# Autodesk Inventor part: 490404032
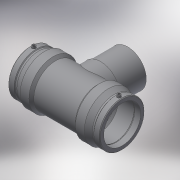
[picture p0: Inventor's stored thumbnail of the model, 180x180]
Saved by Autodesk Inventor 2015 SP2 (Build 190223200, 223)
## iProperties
Created: 2017-06
Part Number: 490404032
Material: Generic
Description: PLASSON TEE 32-32-32
Document SubType Name: Modeling
Designer: KIM
Mass: 90.0221 g
Surface Area: 377.919 cm^2
Volume: 90.0221 cm^3
Density: 1 g/cm^3
Appearance: Default
Author: KIM
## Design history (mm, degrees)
derived "490404.ipt"
feature "Solid1::490404.ipt"
tag "TaggingFeature1"
body "Solid1"
other parameters: "d0" = 104, "d1" = 32, "d2" = 44, "d3" = 39, "d4" = 26, "d5" = 39.6, "d6" = 30.4, "d7" = 32, "d8" = 168 deg, "d10" = 15.6, "d11" = 5.2, "d13" = 104, "d14" = 17.6296, "d17" = 28.8, "d18" = 32, "d19" = 3.52592, "d20" = 168 deg, "d22" = 40.92, "d23" = 44, "d24" = 39.6924, "d25" = 135 deg, "d26" = 72.8, "d27" = 135 deg, "d29" = 43, "d30" = 15, "d31" = 41.6, "d34" = 5 deg, "d35" = 15, "d39" = 5 deg, "d40" = 9.6, "d41" = 4.8, "d42" = 6, "d43" = 0, "d45" = 4, "d46" = 14, "d47" = 0, "d48" = -74, "d49" = 32, "d51" = 0, "d52" = 25.6, "d54" = 0, "d55" = 39.6, "d56" = 44, "d57" = 36.4, "d58" = 135 deg, "d59" = 39, "d60" = 39, "d61" = 135 deg, "d62" = 74, "d72" = 47.32, "d73" = 23.66, "d74" = -74, "d75" = 33.6, "d77" = 0, "d78" = 25.6, "d80" = 0, "d81" = 32, "d82" = 52, "d83" = 0, "d84" = 3, "d85" = 0, "d86" = 3, "d87" = 0, "d88" = 11.31, "d89" = 2.8275, "d90" = 11.31, "d_" = 32, "L_" = 104, "L_1" = 39, "D_" = 44, "A_" = 43, "d_2" = 12, "H_" = 74
